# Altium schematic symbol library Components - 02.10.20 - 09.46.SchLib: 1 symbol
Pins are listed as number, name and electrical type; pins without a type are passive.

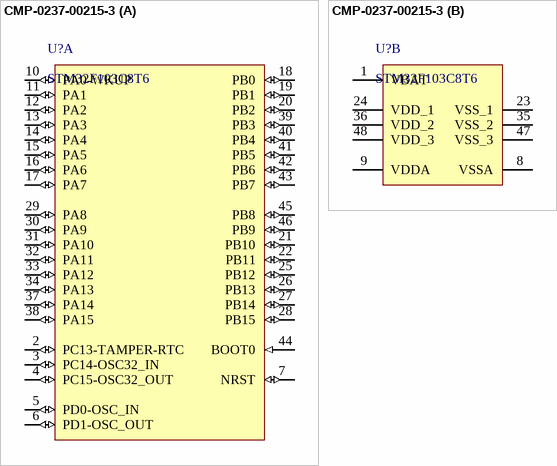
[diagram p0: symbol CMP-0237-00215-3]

## CMP-0237-00215-3
designator U?, comment STM32F103C8T6
ARM Cortex-M3 32-bit MCU, 64 KB Flash, 20 KB Internal RAM, 37 I/Os, 48-pin LQFP, -40 to 85 degC, Tray; Supply Voltage(Vcc) min (V): 2; Internal RAM Size (kB): 20; FLASH Size (Prog) (kB): 64; A/D Converter: 2x12-bit (10 Channel); I/Os (High Current): 37; Operating Frequency(F) (Processor speed) (MHz): 72
footprint STM-LQFP48_L (QFP, 48-Leads, Body 7x7mm, Pitch 0.5mm, IPC High Density)
footprint STM-LQFP48_N (QFP, 48-Leads, Body 7x7mm, Pitch 0.5mm, IPC Medium Density)
footprint STM-LQFP48_M (QFP, 48-Leads, Body 7x7mm, Pitch 0.5mm, IPC Low Density)
part A pins: 2 PC13-TAMPER-RTC (io) "PC13-TAMPER-RTC/PC13/TAMPER-RTC", 3 PC14-OSC32_IN (io) "PC14-OSC32_IN/PC14/OSC32_IN", 4 PC15-OSC32_OUT (io) "PC15-OSC32_OUT/PC15/OSC32_OUT", 5 PD0-OSC_IN (io) "PD0/OSC_IN", 6 PD1-OSC_OUT (io) "PD1/OSC_OUT", 7 NRST (io), 10 PA0-WKUP (io) "PA0-WKUP/PA0/WKUP/USART2_CTS/ADC12_IN0/TIM2_CH1_ETR", 11 PA1 (io) "PA1/USART2_RTS/ADC12_IN1/TIM2_CH2", 12 PA2 (io) "PA2/USART2_TX/ADC12_IN2/TIM2_CH3", 13 PA3 (io) "PA3/USART2_RX/ADC12_IN3/TIM2_CH4", 14 PA4 (io) "PA4/SPI1_NSS/USART2_CK/ADC12_IN4", 15 PA5 (io) "PA5/SPI1_SCK/ADC12_IN5", 16 PA6 (io) "PA6/SPI1_MISO/ADC12_IN6/TIM3_CH1/TIM1_BKIN", 17 PA7 (io) "PA7/SPI1_MOSI/ADC12_IN7/TIM3_CH2/TIM1_CH1N", 18 PB0 (io) "PB0/ADC12_IN8/TIM3_CH3/TIM1_CH2N", 19 PB1 (io) "PB1/ADC12_IN9/TIM3_CH4/TIM1_CH3N", 20 PB2 (io) "PB2/BOOT1", 21 PB10 (io) "PB10/I2C2_SCL/USART3_TX/TIM2_CH3", 22 PB11 (io) "PB11/I2C2_SDA/USART3_RX/TIM2_CH4", 25 PB12 (io) "PB12/SPI2_NSS/I2C2_SMBAl/USART3_CK/TIM1_BKIN", 26 PB13 (io) "PB13/SPI2_SCK/USART3_CTS/TIM1_CH1N", 27 PB14 (io) "PB14/SPI2_MISO/USART3_RTS/TIM1_CH2N", 28 PB15 (io) "PB15/SPI2_MOSI/TIM1_CH3N", 29 PA8 (io) "PA8/USART1_CK/TIM1_CH1/MCO", 30 PA9 (io) "PA9/USART1_TX/TIM1_CH2", 31 PA10 (io) "PA10/USART1_RX/TIM1_CH3", 32 PA11 (io) "PA11/USART1_CTS/CANRX/USBDM/TIM1_CH4", 33 PA12 (io) "PA12/USART1_RTS/CANTX/USBDP/TIM1_ETR", 34 PA13 (io) "PA13/JTMS/SWDIO", 37 PA14 (io) "PA14/JTCK/SWCLK", 38 PA15 (io) "PA15/JTDI/TIM2_CH1_ETR/SPI1_NSS", 39 PB3 (io) "PB3/JTDO/TIM2_CH2/TRACESWO/SPI1_SCK", 40 PB4 (io) "PB4/NJTRST/TIM3_CH1/SPI1_MISO", 41 PB5 (io) "PB5/I2C1_SMBAI/TIM3_CH2/SPI1_MOSI", 42 PB6 (io) "PB6/I2C1_SCL/TIM4_CH1/USART1_TX", 43 PB7 (io) "PB7/I2C1_SDA/TIM4_CH2/USART1_RX", 44 BOOT0 (in), 45 PB8 (io) "PB8/TIM4_CH3/I2C1_SCL/CANRX", 46 PB9 (io) "PB9/TIM4_CH4/I2C1_SDA/CANTX"
part B pins: 1 VBAT (power), 8 VSSA (power), 9 VDDA (power), 23 VSS_1 (power), 24 VDD_1 (power), 35 VSS_2 (power), 36 VDD_2 (power), 47 VSS_3 (power), 48 VDD_3 (power)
